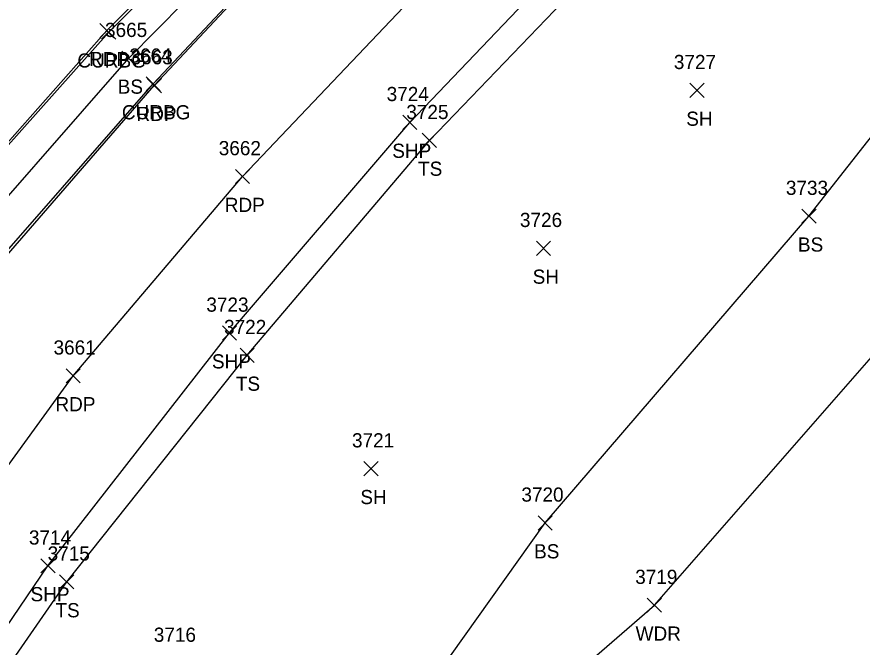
# Model space of a CAD drawing. Extents: x 1623612 to 1625808, y 621345 to 627748.
# Drawn here: x 1625123.8 to 1625243, y 627120.5 to 627209.4 of the extents above; entities that cross this region are included whole.
import ezdxf

# ---------------------------------------------------------------- set-up
doc = ezdxf.new("R2010")
doc.units = 0
for name, color, linetype in [('L_A', 7, 'Continuous'), ('L_I', 7, 'Continuous'), ('L_TIC', 7, 'Continuous'), ('LAWA', 7, 'Continuous'), ('LELB', 7, 'Continuous'), ('LSOGP', 7, 'Continuous'), ('P_A', 7, 'Continuous'), ('P_I', 7, 'Continuous'), ('P_TIC', 7, 'Continuous'), ('PET', 7, 'Continuous'), ('PSP', 7, 'Continuous'), ('R_A', 7, 'Continuous'), ('R_I', 7, 'Continuous'), ('R_TIC', 7, 'Continuous'), ('RC', 7, 'Continuous')]:
    doc.layers.add(name, color=color, linetype=linetype)

msp = doc.modelspace()

# ---------------------------------------------------------------- linework, layer by layer
at = {"layer": 'L_TIC'}
for points in [[(1625138.58, 627202.52), (1625140.58, 627204.52)], [(1625140.58, 627202.52), (1625138.58, 627204.52)], [(1625218.71, 627198), (1625220.71, 627200)], [(1625220.71, 627198), (1625218.71, 627200)], [(1625180.98, 627190.95), (1625182.98, 627192.95)], [(1625182.98, 627190.95), (1625180.98, 627192.95)], [(1625234.5, 627180.26), (1625236.5, 627182.26)], [(1625236.5, 627180.26), (1625234.5, 627182.26)], [(1625197.06, 627175.73), (1625199.06, 627177.73)], [(1625199.06, 627175.73), (1625197.06, 627177.73)], [(1625155.28, 627160.64), (1625157.28, 627162.64)], [(1625157.28, 627160.64), (1625155.28, 627162.64)], [(1625172.75, 627144.66), (1625174.75, 627146.66)], [(1625174.75, 627144.66), (1625172.75, 627146.66)], [(1625197.3, 627137.01), (1625199.3, 627139.01)], [(1625199.3, 627137.01), (1625197.3, 627139.01)], [(1625129.83, 627128.7), (1625131.83, 627130.7)], [(1625131.83, 627128.7), (1625129.83, 627130.7)], [(1625212.7, 627125.41), (1625214.7, 627127.41)], [(1625214.7, 627125.41), (1625212.7, 627127.41)]]:
    msp.add_lwpolyline(points, dxfattribs=at)
at = {"layer": 'LAWA'}
msp.add_lwpolyline([(1625415.15, 627106.89), (1625382.7, 627098.88), (1625336.27, 627080.42), (1625320.48, 627063.82), (1625320.52, 627063.67), (1625304.7, 627054.6), (1625267.78, 627034.56), (1625224.16, 627026.96), (1625202.12, 627004.43), (1625150.28, 626974.64), (1625120.61, 626985.6), (1625102.29, 627003.55), (1625124.36, 627037.24), (1625145.75, 627068.46), (1625178.32, 627095.73), (1625213.7, 627126.41), (1625246.32, 627163.64), (1625275.84, 627203.6), (1625300.5, 627239.13), (1625315, 627239.75)], dxfattribs=at)
at = {"layer": 'LELB'}
for points in [[(1625111, 627101.13), (1625130.83, 627129.7), (1625156.28, 627161.64), (1625181.98, 627191.95), (1625204.33, 627215.18), (1625231.94, 627241.85), (1625257.57, 627263.61), (1625279.76, 627280.38), (1625303.46, 627296.59), (1625337.41, 627320.97), (1625377.29, 627343.7), (1625408.84, 627358.2), (1625449.74, 627375.28), (1625489.49, 627389.68), (1625533.09, 627402.6), (1625571.15, 627412.06), (1625624.18, 627419.27), (1625663.51, 627421.72), (1625706.22, 627423.86), (1625739.39, 627422.48), (1625780.2, 627420.23)], [(1625173.57, 627103.31), (1625198.3, 627138.01), (1625235.5, 627181.26), (1625257.15, 627208.81), (1625262.64, 627212.84), (1625293.35, 627251.67), (1625296.85, 627253.7), (1625299.51, 627255.19), (1625302.1, 627256.94), (1625301.55, 627257.93), (1625312.93, 627281.54), (1625341.78, 627310.69), (1625378.89, 627334.21), (1625411.91, 627351.77), (1625451.38, 627369.19), (1625491.07, 627383.46), (1625534.23, 627395.83), (1625572.47, 627404.98), (1625624.05, 627411.53), (1625663.08, 627414.27), (1625705.62, 627414.88), (1625729.22, 627414.11), (1625728.31, 627412.09)], [(1624882.52, 626691.52), (1624894.84, 626726.31), (1624909.44, 626764.41), (1624928.98, 626811.29), (1624939.98, 626838.67), (1624955.85, 626878.86), (1624972.61, 626920.42), (1624987.1, 626955.93), (1625003.91, 626994.51), (1625020.94, 627031.85), (1625043.24, 627072.63), (1625065.45, 627108.49), (1625090.8, 627145.23), (1625113.09, 627173.27), (1625139.58, 627203.52), (1625166.91, 627231.23), (1625194.44, 627257.76)]]:
    msp.add_lwpolyline(points, dxfattribs=at)
at = {"layer": 'LSOGP'}
msp.add_lwpolyline([(1625178.32, 627095.73), (1625213.7, 627126.41), (1625246.32, 627163.64), (1625275.84, 627203.6), (1625315, 627239.75), (1625343.7, 627269.34), (1625369.47, 627290.4)], dxfattribs=at)
at = {"layer": 'P_TIC'}
for points in [[(1625135.48, 627206.42), (1625137.48, 627208.42)], [(1625137.48, 627206.42), (1625135.48, 627208.42)], [(1625142.18, 627198.67), (1625144.18, 627200.67)], [(1625144.18, 627198.67), (1625142.18, 627200.67)], [(1625178.21, 627193.48), (1625180.21, 627195.48)], [(1625180.21, 627193.48), (1625178.21, 627195.48)], [(1625154.63, 627185.85), (1625156.63, 627187.85)], [(1625156.63, 627185.85), (1625154.63, 627187.85)], [(1625152.78, 627163.79), (1625154.78, 627165.79)], [(1625154.78, 627163.79), (1625152.78, 627165.79)], [(1625130.75, 627157.75), (1625132.75, 627159.75)], [(1625132.75, 627157.75), (1625130.75, 627159.75)], [(1625127.19, 627130.96), (1625129.19, 627132.96)], [(1625129.19, 627130.96), (1625127.19, 627132.96)]]:
    msp.add_lwpolyline(points, dxfattribs=at)
at = {"layer": 'PET'}
for points in [[(1625085.4, 627094.25), (1625110.27, 627129.17), (1625131.75, 627158.75), (1625155.63, 627186.85), (1625182.85, 627215.54), (1625208.2, 627240.19), (1625221.56, 627252.36), (1625248.45, 627276.07), (1625271.93, 627291.03), (1625296.8, 627310.27), (1625331.39, 627331.71), (1625373.16, 627355.88), (1625402.91, 627369.89), (1625447, 627387.72), (1625485.15, 627401.55), (1625532.49, 627414.31), (1625569.15, 627422.13), (1625624.7, 627430.37), (1625663.96, 627433.7), (1625707.55, 627434.84), (1625740.73, 627434.04), (1625783.87, 627430.92)], [(1625060.67, 627111.97), (1625086.82, 627148.78), (1625109.41, 627176.89), (1625136.48, 627207.42), (1625164.04, 627234.95), (1625192.25, 627260.73), (1625198.74, 627265.67), (1625207.6, 627272.69), (1625218.4, 627279.76), (1625228.84, 627285.86), (1625230.54, 627285.08), (1625230.88, 627284.24), (1625230.28, 627283.01), (1625211.12, 627266.85)], [(1625070.59, 627104.96), (1625095.62, 627141.4), (1625117.4, 627170.05), (1625143.18, 627199.67), (1625170.01, 627228.36), (1625196.43, 627253.5), (1625211.12, 627266.85)]]:
    msp.add_lwpolyline(points, dxfattribs=at)
at = {"layer": 'PSP'}
msp.add_lwpolyline([(1625108.38, 627102.81), (1625128.19, 627131.96), (1625153.78, 627164.79), (1625179.21, 627194.48), (1625201.56, 627217.89), (1625229.72, 627244.56), (1625255.64, 627267.13), (1625276.98, 627284.12), (1625300.33, 627301.71), (1625335.15, 627324.9), (1625375.44, 627347.8), (1625406.32, 627362.88), (1625448.69, 627381.31), (1625487.83, 627394.48), (1625532.78, 627406.83), (1625570.78, 627414.59), (1625624.36, 627422.79), (1625663.55, 627425.73), (1625706.52, 627426.77), (1625740.26, 627425.81), (1625780.96, 627423.03)], dxfattribs=at)
at = {"layer": 'R_TIC'}
for points in [[(1625135.75, 627206.21), (1625137.75, 627208.21)], [(1625137.75, 627206.21), (1625135.75, 627208.21)], [(1625142.03, 627198.91), (1625144.03, 627200.91)], [(1625144.03, 627198.91), (1625142.03, 627200.91)]]:
    msp.add_lwpolyline(points, dxfattribs=at)
at = {"layer": 'RC'}
for points in [[(1625070.34, 627105.18), (1625095.35, 627141.59), (1625117.05, 627170.29), (1625143.03, 627199.91), (1625169.85, 627228.56), (1625196.22, 627253.76), (1625210.96, 627267.02)], [(1625060.78, 627111.92), (1625087.16, 627148.54), (1625109.52, 627176.65), (1625136.75, 627207.21), (1625164.2, 627234.89), (1625192.36, 627260.42), (1625198.71, 627265.5)]]:
    msp.add_lwpolyline(points, dxfattribs=at)

# ---------------------------------------------------------------- texts
at = {"layer": 'L_A'}
for s, p in [('BS', (1625138.02, 627198.52)), ('SH', (1625218.2, 627194)), ('TS', (1625180.38, 627186.95)), ('BS', (1625233.95, 627176.26)), ('SH', (1625196.54, 627171.73)), ('TS', (1625154.68, 627156.64)), ('SH', (1625172.24, 627140.66)), ('BS', (1625196.74, 627133.01)), ('TS', (1625129.24, 627124.7)), ('WDR', (1625211.06, 627121.41))]:
    msp.add_text(s, height=2, dxfattribs=at).set_placement(p)
at = {"layer": 'L_I'}
for s, p in [('3665', (1625136.23, 627206.52)), ('3727', (1625216.45, 627202)), ('3725', (1625178.72, 627194.95)), ('3733', (1625232.25, 627184.26)), ('3726', (1625194.74, 627179.73)), ('3722', (1625153.02, 627164.64)), ('3721', (1625171.06, 627148.66)), ('3720', (1625194.95, 627141.01)), ('3715', (1625128.14, 627132.7)), ('3719', (1625211, 627129.41)), ('3716', (1625143.11, 627121.25))]:
    msp.add_text(s, height=2, dxfattribs=at).set_placement(p)
at = {"layer": 'P_A'}
for s, p in [('RDP', (1625133.97, 627202.42)), ('RDP', (1625140.67, 627194.67)), ('SHP', (1625176.74, 627189.48)), ('RDP', (1625153.12, 627181.85)), ('SHP', (1625151.31, 627159.79)), ('RDP', (1625129.24, 627153.75)), ('SHP', (1625125.73, 627126.96))]:
    msp.add_text(s, height=2, dxfattribs=at).set_placement(p)
at = {"layer": 'P_I'}
for s, p in [('3663', (1625139.83, 627202.67)), ('3724', (1625175.95, 627197.48)), ('3662', (1625152.27, 627189.85)), ('3723', (1625150.52, 627167.79)), ('3661', (1625128.97, 627161.75)), ('3714', (1625125.5, 627134.96))]:
    msp.add_text(s, height=2, dxfattribs=at).set_placement(p)
at = {"layer": 'R_A'}
for p in [(1625132.34, 627202.21), (1625138.61, 627194.91)]:
    msp.add_text('CURBG', height=2, dxfattribs=at).set_placement(p)
at = {"layer": 'R_I'}
msp.add_text('3664', height=2, dxfattribs=at).set_placement((1625139.67, 627202.91))

doc.saveas('drawing.dxf')
